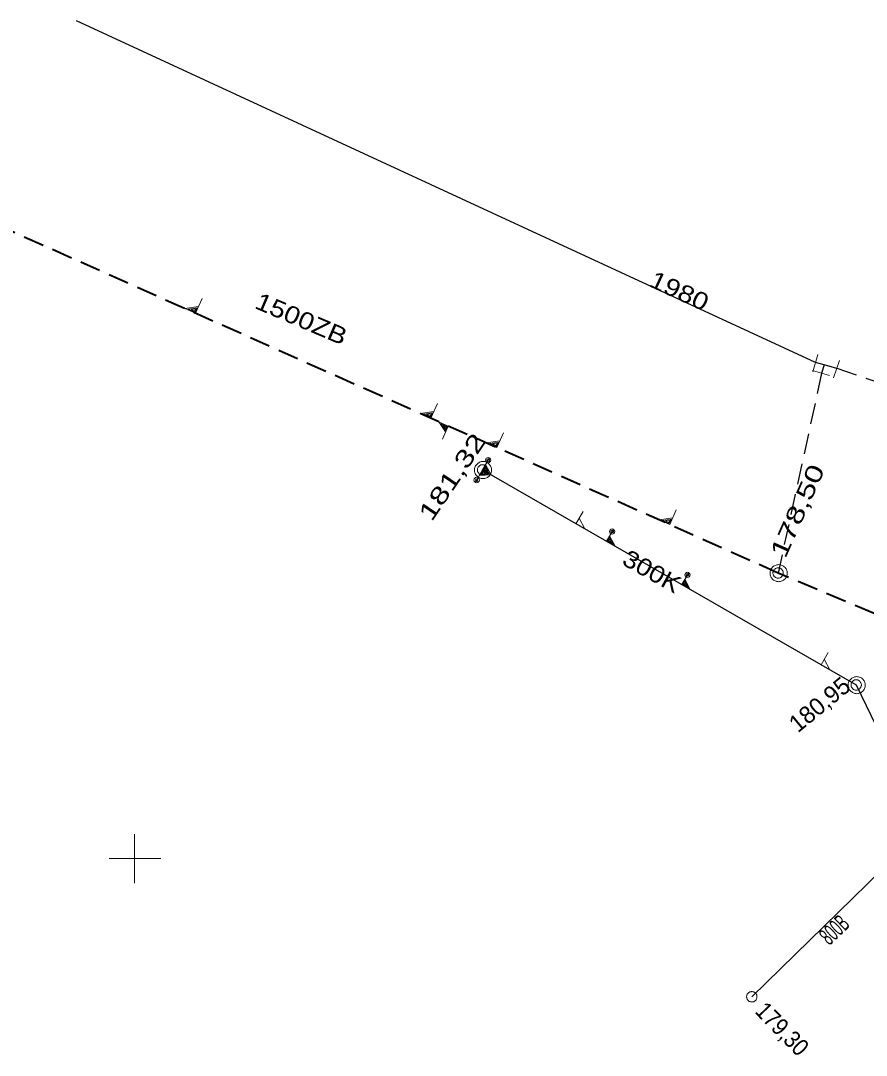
# Model space of a CAD drawing. Extents: x -740851 to -738888, y -1041382 to -1040235.
# Drawn here: x -740406.6 to -740357.5, y -1040411.4 to -1040351.3 of the extents above; entities that cross this region are included whole.
import ezdxf

# ---------------------------------------------------------------- set-up
doc = ezdxf.new("R2010")
doc.units = 0
doc.header["$LTSCALE"] = 0.4
doc.linetypes.add('MEDIUM_DASHED', pattern=[4.5, 3, -1.5])
for name, color, linetype, lineweight in [('1', 7, 'Continuous', 13), ('18', 7, 'Continuous', 13), ('8', 7, 'Continuous', 13)]:
    doc.layers.add(name, color=color, linetype=linetype, lineweight=lineweight)

msp = doc.modelspace()

# ---------------------------------------------------------------- linework, layer by layer
at = {"layer": '1'}
for p, q in [((-740400, -1040398.571), (-740400, -1040401.429)), ((-740400, -1040398.571), (-740400, -1040401.429)), ((-740401.48, -1040400), (-740398.48, -1040400)), ((-740401.48, -1040400), (-740398.48, -1040400))]:
    msp.add_line(p, q, dxfattribs=at)
at = {"layer": '18', "linetype": 'MEDIUM_DASHED', "lineweight": 40}
msp.add_line((-740362.58, -1040383.39), (-740419.3, -1040358.1), dxfattribs=at)
at = {"layer": '18', "lineweight": 25}
msp.add_line((-740379.77, -1040377.39), (-740358.04, -1040389.9), dxfattribs=at)
at = {"layer": '18'}
for points in [[(-740396.083, -1040367.415), (-740396.468, -1040368.278), (-740397.083, -1040368.003), (-740396.294, -1040367.889)], [(-740396.378, -1040367.955), (-740396.49, -1040368.206), (-740396.883, -1040368.031), (-740396.374, -1040367.957)], [(-740396.464, -1040368.025), (-740396.52, -1040368.151), (-740396.722, -1040368.061), (-740396.46, -1040368.027)], [(-740382.384, -1040373.524), (-740382.768, -1040374.386), (-740383.384, -1040374.112), (-740382.595, -1040373.997)], [(-740382.679, -1040374.063), (-740382.79, -1040374.315), (-740383.184, -1040374.139), (-740382.674, -1040374.065)], [(-740382.764, -1040374.134), (-740382.82, -1040374.259), (-740383.022, -1040374.169), (-740382.76, -1040374.136)], [(-740382.101, -1040375.596), (-740381.762, -1040374.837), (-740382.304, -1040374.596), (-740381.915, -1040375.179)], [(-740381.921, -1040375.085), (-740381.822, -1040374.865), (-740382.168, -1040374.71), (-740381.917, -1040375.087)], [(-740381.925, -1040374.988), (-740381.876, -1040374.878), (-740382.053, -1040374.799), (-740381.921, -1040374.99)], [(-740378.548, -1040375.234), (-740378.932, -1040376.097), (-740379.548, -1040375.822), (-740378.759, -1040375.707)], [(-740378.843, -1040375.774), (-740378.954, -1040376.025), (-740379.348, -1040375.85), (-740378.838, -1040375.776)], [(-740378.928, -1040375.844), (-740378.984, -1040375.97), (-740379.186, -1040375.88), (-740378.924, -1040375.846)], [(-740379.371, -1040376.697), (-740379.77, -1040377.39), (-740379.275, -1040377.675), (-740379.59, -1040377.077)], [(-740380.188, -1040378.112), (-740379.773, -1040377.391), (-740379.258, -1040377.687), (-740379.96, -1040377.716)], [(-740379.594, -1040377.168), (-740379.71, -1040377.37), (-740379.394, -1040377.552), (-740379.597, -1040377.166)], [(-740379.599, -1040377.262), (-740379.657, -1040377.362), (-740379.495, -1040377.456), (-740379.602, -1040377.26)], [(-740379.88, -1040377.666), (-740379.76, -1040377.456), (-740379.431, -1040377.645), (-740379.884, -1040377.664)], [(-740379.799, -1040377.612), (-740379.739, -1040377.507), (-740379.57, -1040377.604), (-740379.802, -1040377.61)], [(-740373.927, -1040379.81), (-740374.335, -1040380.519), (-740373.829, -1040380.81), (-740374.151, -1040380.199)], [(-740368.501, -1040379.714), (-740368.886, -1040380.576), (-740369.501, -1040380.302), (-740368.712, -1040380.187)], [(-740368.796, -1040380.253), (-740368.908, -1040380.504), (-740369.301, -1040380.329), (-740368.792, -1040380.255)], [(-740368.882, -1040380.324), (-740368.938, -1040380.449), (-740369.139, -1040380.359), (-740368.877, -1040380.325)], [(-740372.159, -1040380.849), (-740372.558, -1040381.542), (-740372.064, -1040381.826), (-740372.378, -1040381.229)], [(-740372.382, -1040381.319), (-740372.498, -1040381.521), (-740372.182, -1040381.703), (-740372.385, -1040381.318)], [(-740372.388, -1040381.413), (-740372.446, -1040381.514), (-740372.283, -1040381.607), (-740372.391, -1040381.411)], [(-740367.782, -1040383.369), (-740368.181, -1040384.062), (-740367.687, -1040384.346), (-740368.001, -1040383.749)], [(-740368.005, -1040383.839), (-740368.121, -1040384.041), (-740367.805, -1040384.223), (-740368.008, -1040383.838)], [(-740368.01, -1040383.933), (-740368.068, -1040384.034), (-740367.906, -1040384.127), (-740368.014, -1040383.931)], [(-740359.669, -1040388.018), (-740360.077, -1040388.727), (-740359.571, -1040389.018), (-740359.893, -1040388.408)]]:
    msp.add_lwpolyline(points, dxfattribs=at)
for points in [[(-740379.24, -1040377.4), (-740379.25, -1040377.35), (-740379.25, -1040377.3), (-740379.27, -1040377.25), (-740379.29, -1040377.2), (-740379.31, -1040377.15), (-740379.34, -1040377.11), (-740379.37, -1040377.07), (-740379.41, -1040377.03), (-740379.45, -1040377), (-740379.49, -1040376.97), (-740379.54, -1040376.95), (-740379.59, -1040376.93), (-740379.64, -1040376.91), (-740379.69, -1040376.91), (-740379.74, -1040376.9), (-740379.79, -1040376.91), (-740379.84, -1040376.91), (-740379.89, -1040376.93), (-740379.94, -1040376.95), (-740379.99, -1040376.97), (-740380.03, -1040377), (-740380.07, -1040377.03), (-740380.11, -1040377.07), (-740380.14, -1040377.11), (-740380.17, -1040377.15), (-740380.19, -1040377.2), (-740380.21, -1040377.25), (-740380.23, -1040377.3), (-740380.23, -1040377.35), (-740380.24, -1040377.4), (-740380.23, -1040377.45), (-740380.23, -1040377.5), (-740380.21, -1040377.55), (-740380.19, -1040377.6), (-740380.17, -1040377.65), (-740380.14, -1040377.69), (-740380.11, -1040377.73), (-740380.07, -1040377.77), (-740380.03, -1040377.8), (-740379.99, -1040377.83), (-740379.94, -1040377.85), (-740379.89, -1040377.87), (-740379.84, -1040377.89), (-740379.79, -1040377.89), (-740379.74, -1040377.9), (-740379.69, -1040377.89), (-740379.64, -1040377.89), (-740379.59, -1040377.87), (-740379.54, -1040377.85), (-740379.49, -1040377.83), (-740379.45, -1040377.8), (-740379.41, -1040377.77), (-740379.37, -1040377.73), (-740379.34, -1040377.69), (-740379.31, -1040377.65), (-740379.29, -1040377.6), (-740379.27, -1040377.55), (-740379.25, -1040377.5), (-740379.25, -1040377.45)], [(-740379.47, -1040377.39), (-740379.47, -1040377.36), (-740379.476, -1040377.33), (-740379.482, -1040377.3), (-740379.494, -1040377.27), (-740379.512, -1040377.24), (-740379.53, -1040377.216), (-740379.548, -1040377.192), (-740379.572, -1040377.168), (-740379.596, -1040377.15), (-740379.62, -1040377.132), (-740379.65, -1040377.114), (-740379.68, -1040377.102), (-740379.71, -1040377.096), (-740379.74, -1040377.09), (-740379.77, -1040377.09), (-740379.8, -1040377.09), (-740379.83, -1040377.096), (-740379.86, -1040377.102), (-740379.89, -1040377.114), (-740379.92, -1040377.132), (-740379.944, -1040377.15), (-740379.968, -1040377.168), (-740379.992, -1040377.192), (-740380.01, -1040377.216), (-740380.028, -1040377.24), (-740380.046, -1040377.27), (-740380.058, -1040377.3), (-740380.064, -1040377.33), (-740380.07, -1040377.36), (-740380.07, -1040377.39), (-740380.07, -1040377.42), (-740380.064, -1040377.45), (-740380.058, -1040377.48), (-740380.046, -1040377.51), (-740380.028, -1040377.54), (-740380.01, -1040377.564), (-740379.992, -1040377.588), (-740379.968, -1040377.612), (-740379.944, -1040377.63), (-740379.92, -1040377.648), (-740379.89, -1040377.666), (-740379.86, -1040377.678), (-740379.83, -1040377.684), (-740379.8, -1040377.69), (-740379.77, -1040377.69), (-740379.74, -1040377.69), (-740379.71, -1040377.684), (-740379.68, -1040377.678), (-740379.65, -1040377.666), (-740379.62, -1040377.648), (-740379.596, -1040377.63), (-740379.572, -1040377.612), (-740379.548, -1040377.588), (-740379.53, -1040377.564), (-740379.512, -1040377.54), (-740379.494, -1040377.51), (-740379.482, -1040377.48), (-740379.476, -1040377.45), (-740379.47, -1040377.42)], [(-740362.05, -1040383.4), (-740362.06, -1040383.35), (-740362.06, -1040383.3), (-740362.08, -1040383.25), (-740362.1, -1040383.2), (-740362.12, -1040383.15), (-740362.15, -1040383.11), (-740362.18, -1040383.07), (-740362.22, -1040383.03), (-740362.26, -1040383), (-740362.3, -1040382.97), (-740362.35, -1040382.95), (-740362.4, -1040382.93), (-740362.45, -1040382.91), (-740362.5, -1040382.91), (-740362.55, -1040382.9), (-740362.6, -1040382.91), (-740362.65, -1040382.91), (-740362.7, -1040382.93), (-740362.75, -1040382.95), (-740362.8, -1040382.97), (-740362.84, -1040383), (-740362.88, -1040383.03), (-740362.92, -1040383.07), (-740362.95, -1040383.11), (-740362.98, -1040383.15), (-740363, -1040383.2), (-740363.02, -1040383.25), (-740363.04, -1040383.3), (-740363.04, -1040383.35), (-740363.05, -1040383.4), (-740363.04, -1040383.45), (-740363.04, -1040383.5), (-740363.02, -1040383.55), (-740363, -1040383.6), (-740362.98, -1040383.65), (-740362.95, -1040383.69), (-740362.92, -1040383.73), (-740362.88, -1040383.77), (-740362.84, -1040383.8), (-740362.8, -1040383.83), (-740362.75, -1040383.85), (-740362.7, -1040383.87), (-740362.65, -1040383.89), (-740362.6, -1040383.89), (-740362.55, -1040383.9), (-740362.5, -1040383.89), (-740362.45, -1040383.89), (-740362.4, -1040383.87), (-740362.35, -1040383.85), (-740362.3, -1040383.83), (-740362.26, -1040383.8), (-740362.22, -1040383.77), (-740362.18, -1040383.73), (-740362.15, -1040383.69), (-740362.12, -1040383.65), (-740362.1, -1040383.6), (-740362.08, -1040383.55), (-740362.06, -1040383.5), (-740362.06, -1040383.45)], [(-740362.28, -1040383.39), (-740362.28, -1040383.36), (-740362.286, -1040383.33), (-740362.292, -1040383.3), (-740362.304, -1040383.27), (-740362.322, -1040383.24), (-740362.34, -1040383.216), (-740362.358, -1040383.192), (-740362.382, -1040383.168), (-740362.406, -1040383.15), (-740362.43, -1040383.132), (-740362.46, -1040383.114), (-740362.49, -1040383.102), (-740362.52, -1040383.096), (-740362.55, -1040383.09), (-740362.58, -1040383.09), (-740362.61, -1040383.09), (-740362.64, -1040383.096), (-740362.67, -1040383.102), (-740362.7, -1040383.114), (-740362.73, -1040383.132), (-740362.754, -1040383.15), (-740362.778, -1040383.168), (-740362.802, -1040383.192), (-740362.82, -1040383.216), (-740362.838, -1040383.24), (-740362.856, -1040383.27), (-740362.868, -1040383.3), (-740362.874, -1040383.33), (-740362.88, -1040383.36), (-740362.88, -1040383.39), (-740362.88, -1040383.42), (-740362.874, -1040383.45), (-740362.868, -1040383.48), (-740362.856, -1040383.51), (-740362.838, -1040383.54), (-740362.82, -1040383.564), (-740362.802, -1040383.588), (-740362.778, -1040383.612), (-740362.754, -1040383.63), (-740362.73, -1040383.648), (-740362.7, -1040383.666), (-740362.67, -1040383.678), (-740362.64, -1040383.684), (-740362.61, -1040383.69), (-740362.58, -1040383.69), (-740362.55, -1040383.69), (-740362.52, -1040383.684), (-740362.49, -1040383.678), (-740362.46, -1040383.666), (-740362.43, -1040383.648), (-740362.406, -1040383.63), (-740362.382, -1040383.612), (-740362.358, -1040383.588), (-740362.34, -1040383.564), (-740362.322, -1040383.54), (-740362.304, -1040383.51), (-740362.292, -1040383.48), (-740362.286, -1040383.45), (-740362.28, -1040383.42)], [(-740357.51, -1040389.91), (-740357.52, -1040389.86), (-740357.52, -1040389.81), (-740357.54, -1040389.76), (-740357.56, -1040389.71), (-740357.58, -1040389.66), (-740357.61, -1040389.62), (-740357.64, -1040389.58), (-740357.68, -1040389.54), (-740357.72, -1040389.51), (-740357.76, -1040389.48), (-740357.81, -1040389.46), (-740357.86, -1040389.44), (-740357.91, -1040389.42), (-740357.96, -1040389.42), (-740358.01, -1040389.41), (-740358.06, -1040389.42), (-740358.11, -1040389.42), (-740358.16, -1040389.44), (-740358.21, -1040389.46), (-740358.26, -1040389.48), (-740358.3, -1040389.51), (-740358.34, -1040389.54), (-740358.38, -1040389.58), (-740358.41, -1040389.62), (-740358.44, -1040389.66), (-740358.46, -1040389.71), (-740358.48, -1040389.76), (-740358.5, -1040389.81), (-740358.5, -1040389.86), (-740358.51, -1040389.91), (-740358.5, -1040389.96), (-740358.5, -1040390.01), (-740358.48, -1040390.06), (-740358.46, -1040390.11), (-740358.44, -1040390.16), (-740358.41, -1040390.2), (-740358.38, -1040390.24), (-740358.34, -1040390.28), (-740358.3, -1040390.31), (-740358.26, -1040390.34), (-740358.21, -1040390.36), (-740358.16, -1040390.38), (-740358.11, -1040390.4), (-740358.06, -1040390.4), (-740358.01, -1040390.41), (-740357.96, -1040390.4), (-740357.91, -1040390.4), (-740357.86, -1040390.38), (-740357.81, -1040390.36), (-740357.76, -1040390.34), (-740357.72, -1040390.31), (-740357.68, -1040390.28), (-740357.64, -1040390.24), (-740357.61, -1040390.2), (-740357.58, -1040390.16), (-740357.56, -1040390.11), (-740357.54, -1040390.06), (-740357.52, -1040390.01), (-740357.52, -1040389.96)], [(-740357.74, -1040389.9), (-740357.74, -1040389.87), (-740357.746, -1040389.84), (-740357.752, -1040389.81), (-740357.764, -1040389.78), (-740357.782, -1040389.75), (-740357.8, -1040389.726), (-740357.818, -1040389.702), (-740357.842, -1040389.678), (-740357.866, -1040389.66), (-740357.89, -1040389.642), (-740357.92, -1040389.624), (-740357.95, -1040389.612), (-740357.98, -1040389.606), (-740358.01, -1040389.6), (-740358.04, -1040389.6), (-740358.07, -1040389.6), (-740358.1, -1040389.606), (-740358.13, -1040389.612), (-740358.16, -1040389.624), (-740358.19, -1040389.642), (-740358.214, -1040389.66), (-740358.238, -1040389.678), (-740358.262, -1040389.702), (-740358.28, -1040389.726), (-740358.298, -1040389.75), (-740358.316, -1040389.78), (-740358.328, -1040389.81), (-740358.334, -1040389.84), (-740358.34, -1040389.87), (-740358.34, -1040389.9), (-740358.34, -1040389.93), (-740358.334, -1040389.96), (-740358.328, -1040389.99), (-740358.316, -1040390.02), (-740358.298, -1040390.05), (-740358.28, -1040390.074), (-740358.262, -1040390.098), (-740358.238, -1040390.122), (-740358.214, -1040390.14), (-740358.19, -1040390.158), (-740358.16, -1040390.176), (-740358.13, -1040390.188), (-740358.1, -1040390.194), (-740358.07, -1040390.2), (-740358.04, -1040390.2), (-740358.01, -1040390.2), (-740357.98, -1040390.194), (-740357.95, -1040390.188), (-740357.92, -1040390.176), (-740357.89, -1040390.158), (-740357.866, -1040390.14), (-740357.842, -1040390.122), (-740357.818, -1040390.098), (-740357.8, -1040390.074), (-740357.782, -1040390.05), (-740357.764, -1040390.02), (-740357.752, -1040389.99), (-740357.746, -1040389.96), (-740357.74, -1040389.93)], [(-740364.327, -1040408.251), (-740364.306, -1040408.273), (-740364.28, -1040408.29), (-740364.255, -1040408.308), (-740364.225, -1040408.321), (-740364.191, -1040408.33), (-740364.161, -1040408.335), (-740364.131, -1040408.34), (-740364.097, -1040408.34), (-740364.067, -1040408.336), (-740364.037, -1040408.332), (-740364.002, -1040408.324), (-740363.972, -1040408.312), (-740363.946, -1040408.295), (-740363.92, -1040408.278), (-740363.899, -1040408.257), (-740363.877, -1040408.236), (-740363.86, -1040408.21), (-740363.842, -1040408.185), (-740363.829, -1040408.155), (-740363.82, -1040408.121), (-740363.815, -1040408.091), (-740363.81, -1040408.061), (-740363.81, -1040408.027), (-740363.814, -1040407.997), (-740363.818, -1040407.967), (-740363.826, -1040407.932), (-740363.838, -1040407.902), (-740363.855, -1040407.876), (-740363.872, -1040407.85), (-740363.893, -1040407.829), (-740363.914, -1040407.807), (-740363.94, -1040407.79), (-740363.965, -1040407.772), (-740363.995, -1040407.759), (-740364.029, -1040407.75), (-740364.059, -1040407.745), (-740364.089, -1040407.74), (-740364.123, -1040407.74), (-740364.153, -1040407.744), (-740364.183, -1040407.748), (-740364.218, -1040407.756), (-740364.248, -1040407.768), (-740364.274, -1040407.785), (-740364.3, -1040407.802), (-740364.321, -1040407.823), (-740364.343, -1040407.844), (-740364.36, -1040407.87), (-740364.378, -1040407.895), (-740364.391, -1040407.925), (-740364.4, -1040407.959), (-740364.405, -1040407.989), (-740364.41, -1040408.019), (-740364.41, -1040408.053), (-740364.406, -1040408.083), (-740364.402, -1040408.113), (-740364.394, -1040408.148), (-740364.382, -1040408.178), (-740364.365, -1040408.204), (-740364.348, -1040408.23)]]:
    msp.add_lwpolyline(points, close=True, dxfattribs=at)
at = {"layer": '18', "linetype": 'MEDIUM_DASHED', "lineweight": 40}
msp.add_lwpolyline([(-740306.23, -1040407.14), (-740355.337, -1040386.443), (-740362.58, -1040383.39)], dxfattribs=at)
at = {"layer": '18', "lineweight": 25}
msp.add_lwpolyline([(-740358.04, -1040389.9), (-740354.03, -1040398.2), (-740364.11, -1040408.04)], dxfattribs=at)
at = {"layer": '18'}
for centre, radius in [((-740379.444, -1040376.823), 0.151), ((-740379.442, -1040376.822), 0.0744), ((-740380.111, -1040377.979), 0.157), ((-740380.111, -1040377.981), 0.0774), ((-740372.232, -1040380.975), 0.151), ((-740372.231, -1040380.974), 0.0744), ((-740367.855, -1040383.495), 0.151), ((-740367.854, -1040383.494), 0.0744)]:
    msp.add_circle(centre, radius, dxfattribs=at)
at = {"layer": '8', "lineweight": 25}
for p, q in [((-740360.4, -1040371.14), (-740403.38, -1040351.26)), ((-740359.91, -1040371.279), (-740360.05, -1040371.77))]:
    msp.add_line(p, q, dxfattribs=at)
at = {"layer": '8'}
for p, q in [((-740360.553, -1040371.68), (-740360.269, -1040370.68)), ((-740359.353, -1040372.03), (-740359.013, -1040371.03)), ((-740360.59, -1040371.609), (-740359.59, -1040371.907))]:
    msp.add_line(p, q, dxfattribs=at)
at = {"layer": '8', "linetype": 'MEDIUM_DASHED', "lineweight": 25}
msp.add_line((-740360.05, -1040371.77), (-740362.58, -1040383.39), dxfattribs=at)
at = {"layer": '8', "lineweight": 25}
msp.add_lwpolyline([(-740359.17, -1040371.49), (-740359.91, -1040371.279), (-740360.4, -1040371.14)], dxfattribs=at)
at = {"layer": '8', "linetype": 'MEDIUM_DASHED', "lineweight": 25}
msp.add_lwpolyline([(-740297.337, -1040386.803), (-740297.74, -1040385.61), (-740349.498, -1040374.778), (-740359.17, -1040371.49)], dxfattribs=at)

# ---------------------------------------------------------------- texts
at = {"layer": '18'}
for s, rotation, width, p in [('1500ZB', 336.987, 1.2, (-740393.085, -1040367.96)), ('181,32', 55.854, 1.4, (-740382.729, -1040380.445)), ('178,50', 66.031, 1.4, (-740362.165, -1040382.591)), ('300K', 330.847, 1.15, (-740371.73, -1040382.853)), ('800B', 43.272, 0.55, (-740359.601, -1040405.087)), ('179,30', 314.278, 0.9, (-740363.983, -1040408.937))]:
    msp.add_text(s, height=1, rotation=rotation, dxfattribs=dict(at, width=width)).set_placement(p)
msp.add_text('180,95', height=1, rotation=39.509, dxfattribs=at).set_placement((-740361.431, -1040392.722))
at = {"layer": '8', "width": 1.2}
msp.add_text('1980', height=1, rotation=335.177, dxfattribs=at).set_placement((-740370.15, -1040366.678))

doc.saveas('drawing.dxf')
